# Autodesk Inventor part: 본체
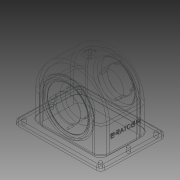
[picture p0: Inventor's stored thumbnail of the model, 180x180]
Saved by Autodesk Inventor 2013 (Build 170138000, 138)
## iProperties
Created: 2015-09
Part Number: 본체
Material: 알루미늄 6061
Document SubType Name: Modeling
Designer: Administrator
Mass: 724.214 g
Surface Area: 890.436 cm^2
Volume: 267.238 cm^3
Density: 2.71 g/cm^3
Author: Administrator
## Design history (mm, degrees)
sketch "스케치1"
  geometry: L1 (70, -52)-(-70, -52); L2 (-70, -52)-(-70, 52); L3 (-70, 52)-(70, 52); L4 (70, 52)-(70, -52); 3 further points
  constraints: 8 end point, 2 midpoint, 2 parallel, 1 horizontal, 1 horizontal alignment, 1 perpendicular, 1 vertical alignment
  dimensions: "d0" = 104 distance of L1.end L2.end; "d2" = 140 distance of L1.start L1.end
extrude "돌출1" new body sketch "스케치1" distance "d3" = 7; taper "d4" = 0 deg
node "작업 평면1"
sketch "스케치2"
  geometry: L1 (140, 0)-(0, 0) reference; L2 (13, 47)-(13, 0); L3 (127, 47)-(127, 0); A1 r 57 centre (70, 47) between (127, 47) and (13, 47); 3 further points
  constraints: 4 end point, 2 midpoint, 2 perpendicular, 2 point on circle, 2 point on line, 2 tangent, 2 vertical alignment, 1 centre point
  dimensions: "d8" = 57 radius of A1; "d10" = 47 distance of L2.start L2.end
extrude "돌출2" join sketch "스케치2" stored distance "d11" = 77; taper "d12" = 0 deg
sketch "스케치3"
  geometry: L1 (140, 0)-(0, 0) reference; L2 (19, 47)-(19, 0); L3 (121, 47)-(121, 0); L4 (19, 0)-(121, 0); A1 r 51 centre (70, 47) between (121, 47) and (19, 47); 2 further points
  constraints: 6 end point, 2 perpendicular, 2 point on circle, 2 point on line, 2 tangent, 1 centre point, 1 collinear, 1 midpoint, 1 vertical alignment
  dimensions: "d14" = 47 distance from line of L1 A1.centre; "d15" = 51 radius of A1
extrude "돌출3" cut sketch "스케치3" stored distance "d16" = 67; taper "d17" = 0 deg
node "작업 평면2"
sketch "스케치4"
  geometry: L1 (0, 0)-(-140, 0) reference; C1 r 31 at (-70, 47); 2 further points
  constraints: 1 centre point, 1 midpoint, 1 vertical alignment
  dimensions: "d19" = 62 diameter of C1; "d20" = 47 distance from line of L1 C1.centre
extrude "돌출4" join sketch "스케치4" stored distance "d21" = 16; taper "d22" = 0 deg
node "작업 평면3"
sketch "스케치5"
  geometry: L1 (140, 0)-(0, 0) reference; C1 r 28 at (70, 47); 2 further points
  constraints: 1 centre point, 1 midpoint, 1 vertical alignment
  dimensions: "d24" = 56 diameter of C1; "d25" = 47 distance from line of L1 C1.centre
extrude "돌출5" join sketch "스케치5" stored distance "d26" = 16; taper "d27" = 40 deg
node "작업 평면4"
sketch "스케치7"
  geometry: C1 r 6 at (0, 0); 1 further point
  constraints: 1 centre point, 1 coincident
  dimensions: "d42" = 12 diameter of C1
extrude "돌출7" join sketch "스케치7" stored distance "d43" = 3; taper "d44" = 10 deg
hole "구멍3" diameter "d58" = 4.459; stored, may be unused: countersink angle "d62" = 90 deg, drill point angle "d64" = 118 deg; dims "d59" = 15, "d60" = 4, "d61" = 2, "d63" = 30, "d134" = 10, "d135" = 10
node "작업 평면5"
sketch "스케치9"
  geometry: L1 (140, 0)-(0, 0) reference; C1 r 33 at (70, 47); 2 further points
  constraints: 1 centre point, 1 midpoint, 1 vertical alignment
  dimensions: "d66" = 66 diameter of C1; "d67" = 47 distance from line of L1 C1.centre
extrude "돌출8" cut sketch "스케치9" stored distance "d68" = 3; taper "d69" = 40 deg
node "작업 평면6"
sketch "스케치10"
  geometry: L1 (140, 0)-(0, 0) reference; C1 r 33 at (70, 47); 2 further points
  constraints: 1 centre point, 1 midpoint, 1 vertical alignment
  dimensions: "d71" = 66 diameter of C1; "d72" = 47 distance from line of L1 C1.centre
extrude "돌출9" join sketch "스케치10" distance "d73" = 3; taper "d74" = 0 deg
hole "구멍4" diameter "d77" = 40; stored, may be unused: countersink angle "d81" = 90 deg, drill point angle "d83" = 118 deg; dims "d75" = 10, "d76" = 10, "d78" = 40, "d79" = 4, "d80" = 2, "d82" = 8
sketch "스케치11"
  geometry: L1 (70, -47)-(-70, -47) reference; C1 r 33 at (0, 0) reference; 3 further points
  constraints: 1 midpoint, 1 vertical alignment
  dimensions: "d84" = 28 distance of C1.centre point (0, 28)
hole "구멍5" sketch "스케치11" at (0, 28) diameter "d85" = 2.459; stored, may be unused: countersink angle "d89" = 90 deg, drill point angle "d91" = 118 deg; dims "d86" = 7, "d87" = 4, "d88" = 2, "d90" = 9
fillet "모깎기1" dims "d95" = 9, "d96" = 14, "d97" = 3, "d98" = 7, "d99" = 0.5
fillet "모깎기2" dims "d100" = 1, "d117" = 3
sketch "스케치12"
  geometry: L1 (-70, 45)-(-70, -45) reference; L2 (70, -45)-(70, 45) reference; L3 (63, 52)-(-63, 52) reference; 7 further points
  constraints: 5 horizontal alignment
  dimensions: "d101" = 44 distance of point (-62, 0) point (-62, -44); "d103" = 44 distance of point (-62, 44) point (-62, 0); "d104" = 44 distance of point (62, 0) point (62, -44); "d105" = 44 distance of point (62, 44) point (62, 0); "d106" = 8 distance from line of point (-62, 44) L1; "d107" = 8 distance from line of point (62, 44) L2; "d108" = 8 distance from line of point (62, 44) L3; "d109" = 8 distance from line of L1 point (-62, -44)
hole "구멍6" sketch "스케치12" at (-62, -44), (-62, 0), (-62, 44), (62, -44), (62, 0), (62, 44) diameter "d110" = 5; stored, may be unused: countersink angle "d114" = 90 deg, drill point angle "d116" = 118 deg; dims "d111" = 7, "d112" = 4, "d113" = 2, "d115" = 9
sketch "스케치13"
  geometry: C1 r 20 at (0, 0) reference; 2 further points
  constraints: 1 vertical alignment
  dimensions: "d118" = 24 distance of C1.centre point (0, 24)
hole "구멍7" sketch "스케치13" at (0, 24) diameter "d119" = 2.459; stored, may be unused: countersink angle "d123" = 90 deg, drill point angle "d125" = 118 deg; dims "d120" = 6, "d121" = 4, "d122" = 2, "d124" = 8
sketch "스케치14"
  geometry: L1 (-20.5, -43)-(69.5, -43) reference; L2 (69.5, -47)-(-20.5, -47) reference; 3 further points
  constraints: 1 midpoint, 1 vertical alignment, 1 other
  dimensions: "d129" = 30 distance from line of L2 point (24.5, -17)
feature "엠보싱1" sketch "스케치14" dims "d0" = 104, "d2" = 140, "d130" = 0.5, "d131" = 0
chamfer "모따기1" distance "d132" = 1; stored, may be unused: second distance "d133" = 2, angle "d136" = 45 deg
node "솔리드1"
pattern_circular "원형 패턴2" dims angle "d93" = 360 deg
pattern_circular "원형 패턴3" dims angle "d127" = 360 deg
other parameters: "d5" = 114, "d6" = 104, "d13" = 102, "d23" = -19, "d65" = -5, "d70" = -3
